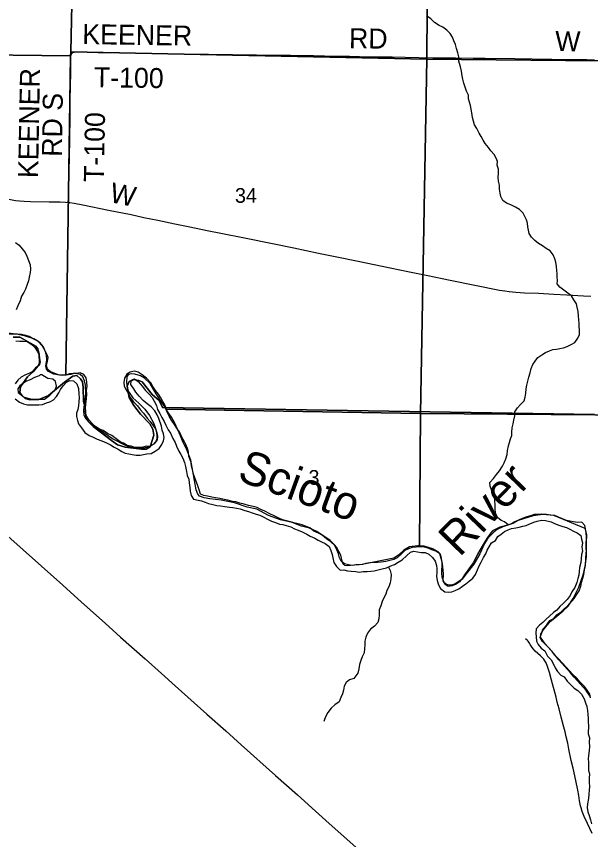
# Model space of a CAD drawing. Extents: x 1584893 to 1934202, y 663575 to 1091909.
# Drawn here: x 1760284 to 1768902, y 925799 to 938155 of the extents above; entities that cross this region are included whole.
import ezdxf

# ---------------------------------------------------------------- set-up
doc = ezdxf.new("R2010")
doc.units = 0
for name, color, linetype in [('GM_X_County_Road', 7, 'Continuous'), ('GM_X_County_Road_Text', 7, 'Continuous'), ('GM_X_Major_River', 7, 'Continuous'), ('GM_X_Major_River_Text', 7, 'Continuous'), ('GM_X_Minor_River', 7, 'Continuous'), ('GM_X_Section', 7, 'Continuous'), ('GM_X_Section_Text', 7, 'Continuous'), ('GM_X_Township', 7, 'Continuous'), ('GM_X_Township_Road', 7, 'Continuous'), ('GM_X_Township_Road_Text', 7, 'Continuous')]:
    doc.layers.add(name, color=color, linetype=linetype)

msp = doc.modelspace()

# ---------------------------------------------------------------- linework, layer by layer
at = {"layer": 'GM_X_County_Road'}
for points in [[(1758465, 935757), (1758657, 935713), (1758914, 935659), (1759091, 935624), (1759381, 935566), (1759590, 935526), (1759977, 935450), (1760170, 935411), (1760267, 935394), (1760331, 935386), (1760397, 935381), (1760495, 935378), (1760774, 935374), (1760938, 935372), (1761020, 935368), (1761062, 935363)], [(1761062, 935363), (1761086, 935361), (1761151, 935351), (1761280, 935326), (1761666, 935248), (1762004, 935180), (1762196, 935138), (1762405, 935097), (1762663, 935044), (1762888, 934998), (1763145, 934944), (1763354, 934903), (1763708, 934831), (1764126, 934746), (1764448, 934680), (1764817, 934604), (1765091, 934548), (1765412, 934481), (1765653, 934431), (1765894, 934382), (1766184, 934324), (1766457, 934269), (1766795, 934199), (1767534, 934048), (1767615, 934034), (1767680, 934025), (1767778, 934016), (1767909, 934008), (1768122, 933999), (1768351, 933988), (1768548, 933977), (1768794, 933963), (1768908, 933954)], [(1760110, 930392), (1760661, 929901), (1760979, 929617), (1761260, 929365), (1761614, 929047), (1761847, 928839), (1762215, 928513), (1762459, 928293), (1762668, 928108), (1763144, 927681), (1763427, 927431), (1763658, 927222), (1764171, 926762), (1764502, 926468), (1764771, 926227), (1764978, 926041), (1765199, 925844), (1765516, 925559)]]:
    msp.add_lwpolyline(points, dxfattribs=at)
at = {"layer": 'GM_X_Major_River'}
for points in [[(1761081, 932788), (1761027, 932769), (1760973, 932764), (1760917, 932777), (1760862, 932794), (1760800, 932819), (1760749, 932866), (1760734, 932916), (1760749, 932978), (1760758, 933038), (1760741, 933088), (1760710, 933143), (1760688, 933195), (1760641, 933254), (1760586, 933291), (1760525, 933322), (1760473, 933349), (1760422, 933368), (1760360, 933381), (1760298, 933384), (1760242, 933387), (1760191, 933386), (1760133, 933379), (1760021, 933348)], [(1760273, 933285), (1760333, 933280), (1760388, 933281), (1760442, 933276), (1760503, 933235), (1760558, 933184), (1760596, 933129), (1760623, 933074), (1760630, 933024), (1760641, 932968), (1760624, 932916), (1760569, 932879), (1760519, 932822), (1760468, 932793), (1760410, 932768), (1760354, 932739), (1760303, 932695), (1760264, 932638)], [(1764010, 930728), (1763950, 930755), (1763895, 930782), (1763839, 930801), (1763769, 930816), (1763700, 930833), (1763638, 930848), (1763577, 930867), (1763525, 930876), (1763455, 930893), (1763402, 930906), (1763336, 930917), (1763270, 930930), (1763215, 930937), (1763153, 930952), (1763099, 930963), (1763046, 930984), (1763027, 931049), (1763006, 931109), (1762987, 931164), (1762962, 931230), (1762943, 931286), (1762924, 931355), (1762911, 931405), (1762904, 931461), (1762873, 931556), (1762864, 931616), (1762849, 931670), (1762826, 931729), (1762803, 931779), (1762766, 931840), (1762735, 931909), (1762689, 931974), (1762656, 932028), (1762609, 932095), (1762576, 932156), (1762547, 932216), (1762530, 932271), (1762509, 932323), (1762482, 932376), (1762451, 932432), (1762416, 932487), (1762372, 932542), (1762330, 932600), (1762299, 932657), (1762238, 932724), (1762169, 932775), (1762113, 932814), (1762052, 932831), (1761990, 932816), (1761939, 932785), (1761906, 932726), (1761897, 932662), (1761900, 932606), (1761929, 932551), (1761966, 932489), (1761997, 932432), (1762042, 932369), (1762099, 932308), (1762140, 932253), (1762189, 932198), (1762246, 932127), (1762289, 932077), (1762330, 932018), (1762369, 931963), (1762392, 931907), (1762401, 931854), (1762396, 931802), (1762351, 931739), (1762293, 931698), (1762231, 931703), (1762167, 931682), (1762113, 931685), (1762061, 931686), (1762005, 931705), (1761948, 931716), (1761892, 931749), (1761839, 931772), (1761778, 931817), (1761713, 931864), (1761649, 931895), (1761586, 931938), (1761531, 931961), (1761477, 931996), (1761426, 932039), (1761375, 932096), (1761330, 932163), (1761315, 932215), (1761318, 932267), (1761327, 932341), (1761334, 932417), (1761340, 932483), (1761337, 932545), (1761343, 932599), (1761342, 932663), (1761328, 932732), (1761293, 932782), (1761241, 932805), (1761189, 932796), (1761137, 932797), (1761081, 932788)], [(1760264, 932414), (1760328, 932367), (1760389, 932340), (1760451, 932326), (1760511, 932323), (1760562, 932325), (1760618, 932326), (1760674, 932329), (1760733, 932356), (1760785, 932369), (1760839, 932400), (1760886, 932451), (1760919, 932505), (1760947, 932556), (1760984, 932610), (1761035, 932663), (1761087, 932688), (1761139, 932685), (1761190, 932638), (1761213, 932568), (1761220, 932487), (1761223, 932437), (1761222, 932369), (1761217, 932309), (1761204, 932253), (1761187, 932200), (1761186, 932150), (1761199, 932091), (1761215, 932039), (1761259, 931978), (1761308, 931911), (1761375, 931866), (1761435, 931841), (1761496, 931812), (1761566, 931787), (1761637, 931755), (1761694, 931724), (1761750, 931691), (1761809, 931658), (1761864, 931625), (1761918, 931598), (1761970, 931588), (1762021, 931579), (1762079, 931568), (1762141, 931571), (1762193, 931578), (1762243, 931589), (1762307, 931596), (1762366, 931627), (1762428, 931670), (1762467, 931729), (1762492, 931783), (1762499, 931837), (1762490, 931891), (1762471, 931947), (1762460, 932006), (1762421, 932118), (1762398, 932175), (1762363, 932235), (1762305, 932294), (1762245, 932340), (1762184, 932389), (1762124, 932454), (1762075, 932515), (1762044, 932567), (1762003, 932628), (1762006, 932684), (1762056, 932713), (1762111, 932674), (1762172, 932607), (1762221, 932542), (1762276, 932485), (1762321, 932434), (1762352, 932382), (1762387, 932313), (1762402, 932257)], [(1760553, 932737), (1760489, 932702), (1760434, 932679), (1760374, 932638), (1760334, 932611), (1760303, 932565), (1760310, 932509), (1760397, 932440), (1760492, 932416), (1760584, 932410), (1760704, 932412), (1760786, 932471), (1760864, 932550), (1760884, 932605), (1760872, 932676), (1760832, 932710), (1760755, 932720), (1760707, 932750), (1760664, 932775), (1760640, 932774), (1760623, 932758)], [(1760623, 932758), (1760553, 932737)], [(1762402, 932257), (1762437, 932196), (1762466, 932136), (1762499, 932075), (1762528, 932018), (1762560, 931950), (1762594, 931899), (1762630, 931818), (1762665, 931760), (1762688, 931703), (1762721, 931631), (1762752, 931580), (1762779, 931524), (1762804, 931461), (1762821, 931401), (1762836, 931326), (1762847, 931264), (1762870, 931210), (1762877, 931153), (1762888, 931085), (1762891, 931027), (1762904, 930965), (1762943, 930910), (1763010, 930893), (1763062, 930886), (1763118, 930863), (1763169, 930846), (1763231, 930827), (1763292, 930816), (1763346, 930809), (1763412, 930798), (1763480, 930791), (1763531, 930784), (1763589, 930773), (1763643, 930764), (1763712, 930739), (1763766, 930726), (1763824, 930703), (1763881, 930684), (1763937, 930667), (1763996, 930638), (1764051, 930607), (1764113, 930578), (1764172, 930557), (1764230, 930532), (1764284, 930529), (1764335, 930512), (1764403, 930494), (1764456, 930464), (1764514, 930443), (1764571, 930420), (1764641, 930382), (1764694, 930353), (1764761, 930322), (1764813, 930293), (1764864, 930268), (1764918, 930245), (1764979, 930196), (1765004, 930136), (1765025, 930079), (1765034, 930029), (1765049, 929959), (1765086, 929896), (1765143, 929843), (1765197, 929848), (1765252, 929835), (1765310, 929830), (1765376, 929823), (1765430, 929812), (1765490, 929821), (1765550, 929822), (1765604, 929827), (1765656, 929834), (1765714, 929849), (1765774, 929862), (1765840, 929879), (1765906, 929906), (1765959, 929929), (1766015, 929964), (1766076, 929999), (1766138, 930060), (1766199, 930111), (1766251, 930126), (1766303, 930119), (1766359, 930108), (1766419, 930107), (1766474, 930084), (1766531, 930035), (1766570, 929979), (1766591, 929914), (1766596, 929864), (1766593, 929804), (1766588, 929752), (1766599, 929688), (1766620, 929624), (1766649, 929569), (1766714, 929516), (1766770, 929513), (1766822, 929518), (1766872, 929539), (1766927, 929564)], [(1768843, 930198), (1768842, 930252), (1768844, 930372), (1768829, 930436), (1768815, 930513), (1768770, 930565), (1768704, 930557), (1768646, 930568), (1768592, 930579), (1768540, 930591), (1768479, 930613), (1768421, 930640), (1768364, 930663), (1768308, 930670), (1768240, 930677), (1768173, 930682), (1768109, 930681), (1768057, 930678), (1768001, 930661), (1767945, 930646), (1767876, 930619), (1767822, 930594), (1767766, 930567), (1767715, 930540), (1767649, 930517), (1767599, 930504), (1767541, 930491), (1767478, 930460), (1767428, 930434), (1767391, 930383), (1767346, 930320), (1767305, 930254), (1767275, 930203), (1767242, 930145), (1767207, 930082), (1767174, 930020), (1767141, 929953), (1767100, 929896), (1767049, 929828), (1767010, 929775), (1766979, 929721), (1766936, 929666), (1766884, 929631), (1766826, 929606), (1766764, 929599), (1766712, 929632), (1766695, 929682), (1766674, 929737), (1766669, 929797), (1766668, 929849), (1766673, 929907), (1766676, 929963), (1766659, 930017), (1766638, 930088), (1766577, 930129), (1766519, 930148), (1766464, 930175), (1766410, 930190), (1766344, 930193), (1766282, 930188), (1766222, 930183), (1766170, 930164), (1766114, 930137), (1766053, 930078), (1766000, 930029), (1765948, 930003), (1765890, 929988), (1765830, 929971), (1765758, 929965), (1765702, 929958), (1765646, 929957), (1765588, 929952), (1765530, 929941), (1765480, 929929), (1765430, 929922), (1765378, 929921), (1765324, 929914), (1765270, 929925), (1765208, 929938), (1765157, 929977), (1765134, 930027), (1765119, 930090), (1765094, 930148), (1765061, 930215), (1765004, 930266), (1764943, 930307), (1764872, 930366), (1764819, 930397), (1764749, 930428), (1764686, 930480), (1764631, 930497), (1764573, 930522), (1764513, 930539), (1764450, 930554), (1764398, 930567), (1764337, 930584), (1764279, 930601), (1764214, 930630), (1764152, 930659), (1764087, 930690), (1764010, 930728)], [(1766927, 929564), (1766981, 929601), (1767032, 929638), (1767082, 929678), (1767133, 929723), (1767176, 929780), (1767207, 929850), (1767230, 929909), (1767261, 929963), (1767296, 930032), (1767329, 930088), (1767351, 930143), (1767380, 930195), (1767415, 930254), (1767474, 930289), (1767510, 930349), (1767561, 930384), (1767612, 930425), (1767666, 930450), (1767716, 930467), (1767778, 930476), (1767828, 930488), (1767884, 930503), (1767936, 930516), (1767989, 930537), (1768051, 930562), (1768101, 930579), (1768165, 930594), (1768225, 930591), (1768311, 930569), (1768362, 930544), (1768427, 930517), (1768485, 930498), (1768539, 930485), (1768592, 930458), (1768648, 930427), (1768699, 930401), (1768754, 930362), (1768767, 930309), (1768780, 930253), (1768773, 930187), (1768780, 930129), (1768766, 930077), (1768762, 930011), (1768754, 929959), (1768738, 929883), (1768731, 929821), (1768727, 929769), (1768710, 929716), (1768695, 929660), (1768664, 929582), (1768623, 929519), (1768596, 929465), (1768549, 929402), (1768492, 929345), (1768439, 929296), (1768396, 929241), (1768344, 929205), (1768287, 929152), (1768237, 929109), (1768186, 929056), (1768135, 929017), (1768084, 928960), (1768079, 928896), (1768084, 928840), (1768089, 928777), (1768115, 928727), (1768162, 928674), (1768217, 928631), (1768257, 928554), (1768310, 928497), (1768341, 928441), (1768372, 928378), (1768405, 928324), (1768454, 928269), (1768508, 928240), (1768549, 928179), (1768604, 928124), (1768655, 928071), (1768710, 928034), (1768767, 927979), (1768806, 927912), (1768827, 927852), (1768848, 927794), (1768857, 927737), (1768860, 927677), (1768867, 927621), (1768866, 927563), (1768869, 927509), (1768867, 927387), (1768886, 927328), (1768881, 927259), (1768884, 927194), (1768879, 927134), (1768870, 927063), (1768867, 927011), (1768870, 926960), (1768869, 926910), (1768872, 926838), (1768885, 926784), (1768882, 926720)], [(1768902, 927927), (1768891, 927979), (1768850, 928044), (1768813, 928096), (1768748, 928160), (1768695, 928223), (1768636, 928278), (1768585, 928333), (1768536, 928387), (1768483, 928446), (1768422, 928511), (1768367, 928568), (1768328, 928621), (1768283, 928672), (1768232, 928721), (1768181, 928772), (1768146, 928833), (1768171, 928902), (1768188, 928958), (1768245, 929021), (1768292, 929088), (1768351, 929119), (1768397, 929173), (1768460, 929215), (1768511, 929267), (1768563, 929310), (1768657, 929420), (1768690, 929472), (1768731, 929535), (1768754, 929605), (1768767, 929657), (1768784, 929724), (1768799, 929778), (1768812, 929850), (1768827, 929910), (1768833, 930022), (1768836, 930090), (1768842, 930142), (1768843, 930198)], [(1768882, 926720), (1768881, 926654), (1768884, 926596), (1768881, 926542), (1768878, 926482), (1768869, 926414), (1768858, 926334), (1768851, 926280), (1768862, 926214), (1768881, 926162), (1768901, 926095), (1768918, 926037)]]:
    msp.add_lwpolyline(points, dxfattribs=at)
at = {"layer": 'GM_X_Minor_River'}
for points in [[(1767535, 935624), (1767518, 935684), (1767515, 935743), (1767522, 935798), (1767521, 935861), (1767500, 935921), (1767505, 935979), (1767484, 936029), (1767457, 936084), (1767404, 936137), (1767371, 936190), (1767318, 936246), (1767292, 936297), (1767261, 936352), (1767232, 936404), (1767194, 936475), (1767158, 936526), (1767143, 936586), (1767132, 936640), (1767121, 936708), (1767110, 936765), (1767099, 936819), (1767086, 936869), (1767071, 936921), (1767070, 936974), (1767041, 937032), (1767020, 937093), (1767001, 937155), (1766986, 937215), (1766975, 937265), (1766966, 937336), (1766949, 937400), (1766927, 937483), (1766926, 937549), (1766909, 937607), (1766890, 937675), (1766873, 937732), (1766852, 937788), (1766829, 937843), (1766796, 937901), (1766743, 937950), (1766683, 937995), (1766628, 938022), (1766559, 938065), (1766504, 938118), (1766441, 938166)], [(1767667, 930523), (1767612, 930571), (1767560, 930590), (1767507, 930635), (1767478, 930688), (1767469, 930748), (1767468, 930826), (1767465, 930886), (1767460, 930944), (1767447, 930999), (1767416, 931051), (1767395, 931104), (1767390, 931160), (1767447, 931221), (1767490, 931278), (1767535, 931335), (1767580, 931405), (1767607, 931456), (1767629, 931512), (1767648, 931580), (1767653, 931638), (1767671, 931708), (1767685, 931759), (1767698, 931813), (1767719, 931867), (1767720, 931917), (1767727, 931979), (1767742, 932041), (1767751, 932093), (1767766, 932160), (1767763, 932220), (1767806, 932280), (1767852, 932331), (1767903, 932384), (1767918, 932438), (1767929, 932500), (1767936, 932564), (1767945, 932618), (1767958, 932678), (1767975, 932739), (1767994, 932805), (1768011, 932869), (1768036, 932931), (1768069, 932982), (1768113, 933037), (1768172, 933078), (1768226, 933111), (1768285, 933138), (1768337, 933158), (1768393, 933163), (1768443, 933172), (1768497, 933181), (1768551, 933200), (1768612, 933229), (1768668, 933260), (1768711, 933325), (1768736, 933383), (1768737, 933445), (1768732, 933499), (1768729, 933549), (1768726, 933603), (1768720, 933660), (1768718, 933728), (1768701, 933790), (1768689, 933840), (1768653, 933899), (1768616, 933962), (1768560, 934003), (1768501, 934048), (1768442, 934089), (1768401, 934140), (1768404, 934192), (1768399, 934244), (1768399, 934294), (1768394, 934344), (1768391, 934404), (1768382, 934466), (1768365, 934517), (1768342, 934579), (1768295, 934638), (1768238, 934673), (1768183, 934710), (1768123, 934745), (1768068, 934790), (1768013, 934841), (1767980, 934896), (1767969, 934948), (1767962, 934998), (1767953, 935050), (1767938, 935101), (1767916, 935151), (1767891, 935203), (1767834, 935259), (1767775, 935290), (1767704, 935325), (1767642, 935350), (1767587, 935393), (1767554, 935454), (1767543, 935504), (1767536, 935562), (1767535, 935624)], [(1760269, 934762), (1760322, 934721), (1760367, 934667), (1760414, 934610), (1760439, 934557), (1760462, 934491), (1760489, 934426), (1760494, 934362), (1760487, 934310), (1760476, 934240), (1760463, 934186), (1760446, 934129), (1760417, 934063), (1760396, 934009), (1760361, 933956), (1760338, 933884), (1760305, 933809), (1760280, 933749)], [(1765867, 929890), (1765893, 929836), (1765908, 929776), (1765905, 929714), (1765896, 929654), (1765875, 929594), (1765846, 929539), (1765827, 929481), (1765801, 929427), (1765776, 929374), (1765753, 929306), (1765730, 929246), (1765729, 929174), (1765724, 929110), (1765707, 929057), (1765660, 929003), (1765597, 928956), (1765552, 928897), (1765529, 928836), (1765512, 928778), (1765514, 928724), (1765507, 928664), (1765502, 928604), (1765473, 928540), (1765452, 928485), (1765431, 928427), (1765422, 928361), (1765407, 928297), (1765346, 928216), (1765285, 928197), (1765233, 928158), (1765204, 928103), (1765195, 928043), (1765180, 927987), (1765155, 927929), (1765126, 927868), (1765062, 927819), (1765009, 927770), (1764956, 927704), (1764923, 927643), (1764902, 927585), (1764898, 927571)]]:
    msp.add_lwpolyline(points, dxfattribs=at)
at = {"layer": 'GM_X_Section'}
for points in [[(1755981, 942886), (1761209, 942861), (1761100, 937622), (1761097, 937566), (1755912, 937626)], [(1761209, 942861), (1766481, 942794), (1766444, 937515), (1761100, 937622)], [(1766481, 942794), (1771824, 942715), (1771650, 937464), (1766444, 937515)], [(1761097, 937566), (1761100, 937622), (1766444, 937515), (1766347, 932193), (1762525, 932258), (1762512, 932294), (1762381, 932489), (1762290, 932644), (1762205, 932724), (1762145, 932759), (1762059, 932786), (1762009, 932790), (1761965, 932780), (1761943, 932752), (1761938, 932662), (1761951, 932560), (1761975, 932508), (1762032, 932430), (1762122, 932351), (1762213, 932258), (1762281, 932166), (1762346, 932047), (1762377, 931955), (1762392, 931875), (1762392, 931813), (1762374, 931773), (1762335, 931729), (1762265, 931688), (1762167, 931667), (1762089, 931665), (1762007, 931682), (1761921, 931714), (1761724, 931816), (1761481, 931984), (1761407, 932036), (1761328, 932109), (1761302, 932165), (1761295, 932245), (1761323, 932489), (1761320, 932619), (1761306, 932687), (1761279, 932743), (1761241, 932778), (1761195, 932792), (1761145, 932795), (1761099, 932781), (1761023, 932769)], [(1766444, 937515), (1771650, 937464), (1771578, 932153), (1766347, 932193)], [(1762525, 932258), (1766347, 932193), (1766334, 930209), (1766308, 930209), (1766182, 930192), (1766098, 930143), (1766021, 930067), (1765947, 930024), (1765474, 929929), (1765248, 929909), (1765212, 929915), (1765196, 929927), (1765180, 929960), (1765151, 930066), (1765090, 930186), (1765060, 930223), (1764991, 930287), (1764792, 930425), (1764684, 930473), (1764564, 930504), (1764425, 930557), (1764249, 930601), (1764065, 930666), (1763892, 930761), (1763746, 930791), (1763559, 930852), (1763355, 930894), (1763187, 930915), (1763101, 930929), (1763033, 930956), (1763004, 930984), (1762980, 931048), (1762932, 931327), (1762900, 931495), (1762837, 931664), (1762786, 931758), (1762744, 931860), (1762660, 932051), (1762610, 932139)]]:
    msp.add_lwpolyline(points, close=True, dxfattribs=at)
for points in [[(1755912, 937626), (1761097, 937566), (1761023, 932769), (1760931, 932768), (1760847, 932785), (1760763, 932825), (1760734, 932858), (1760724, 932910), (1760741, 933002), (1760737, 933072), (1760716, 933138), (1760676, 933208), (1760603, 933283), (1760543, 933317), (1760421, 933358), (1760307, 933383), (1760160, 933402)], [(1768903, 927939), (1768838, 928034), (1768751, 928130), (1768654, 928237), (1768602, 928303), (1768428, 928495), (1768344, 928597), (1768221, 928736), (1768152, 928835), (1768154, 928881), (1768189, 928943), (1768294, 929072), (1768368, 929125), (1768489, 929230), (1768566, 929302), (1768641, 929417), (1768724, 929587), (1768797, 929790), (1768825, 929930), (1768843, 930046), (1768837, 930240), (1768840, 930326), (1768836, 930414), (1768819, 930468), (1768350, 930664), (1768184, 930679), (1768038, 930660), (1767815, 930588), (1767733, 930546), (1767587, 930495), (1767500, 930454), (1767452, 930414), (1767359, 930325), (1767309, 930244), (1767240, 930088), (1767148, 929933), (1767037, 929786), (1766975, 929710), (1766882, 929645), (1766822, 929619), (1766780, 929619), (1766740, 929630), (1766698, 929658), (1766690, 929676), (1766693, 929794), (1766680, 929938), (1766653, 930068), (1766639, 930093), (1766614, 930117), (1766536, 930163), (1766402, 930204), (1766334, 930209), (1766347, 932193), (1771578, 932153)]]:
    msp.add_lwpolyline(points, dxfattribs=at)
at = {"layer": 'GM_X_Township'}
for points in [[(1768959, 932180), (1762476, 932287), (1762426, 932390), (1762319, 932480), (1762170, 932669), (1762119, 932691), (1762037, 932707), (1761978, 932677), (1761945, 932607), (1761976, 932437), (1762048, 932315), (1762147, 932185), (1762285, 932039), (1762332, 931962), (1762346, 931870), (1762291, 931696), (1762230, 931658), (1762161, 931657), (1761917, 931691), (1761801, 931726), (1761710, 931788), (1761436, 932000), (1761360, 932077), (1761324, 932157), (1761313, 932285), (1761290, 932374), (1761286, 932584), (1761274, 932669), (1761246, 932715), (1761189, 932765), (1761130, 932754), (1761004, 932666), (1760766, 932467), (1760621, 932407), (1760486, 932399), (1760412, 932420), (1760368, 932462), (1760335, 932509), (1760342, 932595), (1760450, 932743), (1760534, 932821), (1760611, 932912), (1760628, 932956), (1760625, 933086), (1760603, 933166), (1760574, 933206), (1760335, 933343), (1760233, 933343)], [(1760233, 933343), (1760335, 933343), (1760574, 933206), (1760603, 933166), (1760625, 933086), (1760628, 932956), (1760611, 932912), (1760534, 932821), (1760450, 932743), (1760342, 932595), (1760335, 932509), (1760368, 932462), (1760412, 932420), (1760486, 932399), (1760621, 932407), (1760766, 932467), (1761004, 932666), (1761130, 932754), (1761189, 932765), (1761246, 932715), (1761274, 932669), (1761286, 932584), (1761290, 932374), (1761313, 932285), (1761324, 932157), (1761360, 932077), (1761436, 932000), (1761710, 931788), (1761801, 931726), (1761917, 931691), (1762161, 931657), (1762230, 931658), (1762291, 931696), (1762346, 931870), (1762332, 931962), (1762285, 932039), (1762147, 932185), (1762048, 932315), (1761976, 932437), (1761945, 932607), (1761978, 932677), (1762037, 932707), (1762119, 932691), (1762170, 932669), (1762319, 932480), (1762426, 932390), (1762476, 932287), (1768959, 932180)]]:
    msp.add_lwpolyline(points, dxfattribs=at)
at = {"layer": 'GM_X_Township_Road'}
for points in [[(1761062, 935363), (1761064, 935421), (1761071, 935634), (1761079, 936042), (1761085, 936320), (1761088, 936647), (1761092, 936925), (1761094, 937089), (1761098, 937334), (1761099, 937514), (1761100, 937546), (1761102, 937562), (1761107, 937578), (1761110, 937589), (1761117, 937601)], [(1761117, 937601), (1761124, 937609), (1761132, 937614), (1761139, 937617), (1761149, 937620), (1761162, 937622), (1761180, 937623), (1761278, 937622), (1761508, 937616), (1761870, 937609), (1762346, 937601), (1762740, 937595), (1763167, 937590), (1763889, 937579), (1764119, 937576), (1764267, 937574), (1764398, 937574), (1764562, 937571), (1764743, 937568), (1764907, 937564), (1765088, 937561), (1765285, 937557), (1765432, 937555), (1765662, 937551), (1765924, 937547), (1766121, 937543), (1766532, 937535), (1766745, 937534), (1766877, 937533), (1767139, 937530), (1767320, 937529), (1767763, 937522), (1768026, 937520), (1768322, 937515), (1768634, 937511), (1768847, 937508), (1768963, 937506)], [(1768927, 925891), (1768856, 926039), (1768807, 926143), (1768777, 926219), (1768761, 926274), (1768752, 926307), (1768737, 926379), (1768724, 926462), (1768711, 926540), (1768682, 926685), (1768641, 926870), (1768613, 926987), (1768577, 927158), (1768559, 927245), (1768537, 927343), (1768520, 927415), (1768502, 927486), (1768463, 927635), (1768432, 927762), (1768403, 927862), (1768384, 927936), (1768314, 928194), (1768284, 928305), (1768256, 928399), (1768236, 928450), (1768226, 928466), (1768214, 928483), (1768199, 928506), (1768181, 928527), (1768153, 928555), (1768073, 928626), (1768044, 928658), (1768026, 928680), (1768014, 928699), (1767997, 928728), (1767985, 928748), (1767965, 928775), (1767950, 928790), (1767923, 928811)]]:
    msp.add_lwpolyline(points, dxfattribs=at)

# ---------------------------------------------------------------- texts
at = {"layer": 'GM_X_County_Road_Text'}
msp.add_text('W', height=300, rotation=348.4058, dxfattribs=at).set_placement((1761669, 935372))
at = {"layer": 'GM_X_Major_River_Text'}
for s, rotation, p in [('Scioto', 340.0119, (1763580, 931199)), ('River', 46.0271, (1766934, 930029))]:
    msp.add_text(s, height=500.1, rotation=rotation, dxfattribs=at).set_placement(p)
at = {"layer": 'GM_X_Section_Text'}
for s, p in [('34', (1763564, 935358)), ('3', (1764668, 931125))]:
    msp.add_text(s, height=221, rotation=0, dxfattribs=at).set_placement(p)
at = {"layer": 'GM_X_Township_Road_Text'}
for s, rotation, p in [('KEENER', 359.135, (1761270, 937741)), ('RD', 359.089, (1765274, 937680)), ('W', 359.2724, (1768370, 937636)), ('KEENER', 88.9606, (1760608, 935727)), ('T-100', 359.1913, (1761444, 937094)), ('RD S', 89.0606, (1760965, 936047)), ('T-100', 88.877, (1761594, 935668))]:
    msp.add_text(s, height=300, rotation=rotation, dxfattribs=at).set_placement(p)

doc.saveas('drawing.dxf')
